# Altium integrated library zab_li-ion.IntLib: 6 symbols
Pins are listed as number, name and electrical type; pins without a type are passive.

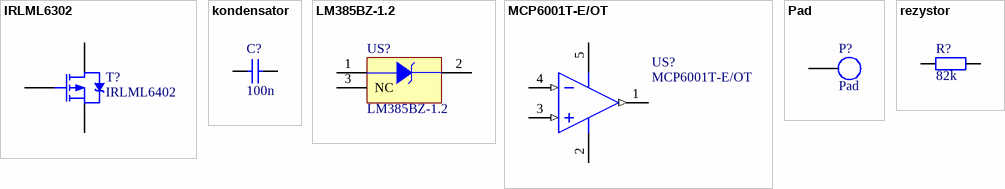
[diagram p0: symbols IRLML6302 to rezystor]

## IRLML6302
designator T?, comment IRLML6402
HEXFET Power MOSFET
footprint SOT-23 (SOT-23; 3 Leads; Body 3.1 x 2.5 mm, inc. leads (LxW max))
simulation model IRLML6302 (SUBCKT)
pins: 1 G, 2 S, 3 D

## kondensator
designator C?, comment 100n
footprint kond 2,5mm
footprint kond 5mm
footprint kond 7,5mm
footprint kond 10mm
footprint MELF-0805 (Metal Electrode Face (MELF) Resistor; Body 2 x 1.4 mm (LxDia))
footprint MELF-1206 (Metal Electrode Face (MELF) Resistor; Body 3.2 x 1.8 mm (LxDia))
footprint kond 15mm
pins: 1, 2

## LM385BZ-1.2
designator US?
Micropower Voltage Reference Diode
footprint 29-04 (TO, Flat Index; 3 In-Line, Axial Leads; Body Dia. 4.8mm; Leads 0.48 x 0.5 mm (max))
pins: 1 A, 2 K, 3 NC

## MCP6001T-E/OT
designator US?
1 MHz, Low-Power Operational Amplifier, 5-Pin SOT-23, Extended Temperature, Tape and Reel
footprint SOT-23-OT5_N (SOT23, 5-Leads, Body 2.9x1.6mm, Pitch 0.95mm, Lead Span 2.7mm, IPC Medium Density)
footprint SOT-23-OT5_L (SOT23, 5-Leads, Body 2.9x1.6mm, Pitch 0.95mm, Lead Span 2.7mm, IPC High Density)
footprint SOT-23-OT5_M (SOT23, 5-Leads, Body 2.9x1.6mm, Pitch 0.95mm, Lead Span 2.7mm, IPC Low Density)
pins: 1 VOUT (out), 2 VSS (power), 3 VIN+ (in), 4 VIN- (in), 5 VDD (power)

## Pad
designator P?
footprint pad fi 0,8mm
footprint pad fi 1,5mm
footprint pad fi 1mm
footprint pad fi 2mm
footprint pad fi 2,5mm
pins: 1

## rezystor
designator R?, comment 82k
footprint rez 7,5mm
footprint rez 10mm
footprint rez 12,5mm
footprint rez 15mm
footprint rez 17,5mm
footprint MELF-0805 (Metal Electrode Face (MELF) Resistor; Body 2 x 1.4 mm (LxDia))
footprint MELF-1206 (Metal Electrode Face (MELF) Resistor; Body 3.2 x 1.8 mm (LxDia))
footprint rez_bocznik 20mm
pins: 1, 2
